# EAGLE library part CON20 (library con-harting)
CONNECTOR
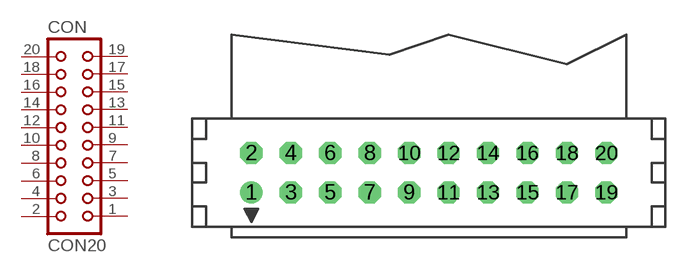
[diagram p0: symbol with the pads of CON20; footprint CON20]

Designator prefix CON

## CON20 (OC_FARNELL: unknown; OC_NEWARK: unknown)  [CON20]
1  1  pas
2  2  pas
3  3  pas
4  4  pas
5  5  pas
6  6  pas
7  7  pas
8  8  pas
9  9  pas
10  10  pas
11  11  pas
12  12  pas
13  13  pas
14  14  pas
15  15  pas
16  16  pas
17  17  pas
18  18  pas
19  19  pas
20  20  pas

## Footprint CON20 (pad centres in mm)
CONNECTOR
drill 0.914 round: 1 -11.43,-1.27
drill 0.914 octagon: 2 -11.43,1.27; 3 -8.89,-1.27; 4 -8.89,1.27; 5 -6.35,-1.27; 6 -6.35,1.27; 7 -3.81,-1.27; 8 -3.81,1.27; 9 -1.27,-1.27; 10 -1.27,1.27; 11 1.27,-1.27; 12 1.27,1.27; 13 3.81,-1.27; 14 3.81,1.27; 15 6.35,-1.27; 16 6.35,1.27; 17 8.89,-1.27; 18 8.89,1.27; 19 11.43,-1.27; 20 11.43,1.27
